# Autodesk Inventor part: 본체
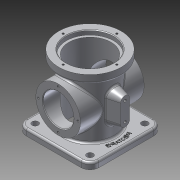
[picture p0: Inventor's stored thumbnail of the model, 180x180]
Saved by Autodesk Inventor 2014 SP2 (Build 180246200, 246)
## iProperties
Created: 2021-03
Part Number: 본체
Material: 알루미늄 6061
Document SubType Name: Modeling
Designer: 거성
Density: 2.71 g/cm^3
Appearance: 알루미늄 - 평지
Author: 거성
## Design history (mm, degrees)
sketch "스케치1"
  geometry: L1 (57, 57)-(-57, 57); L2 (-57, 57)-(-57, -57); L3 (-57, -57)-(57, -57); L4 (57, -57)-(57, 57); L5 (57, 57)-(-57, -57); L6 (-57, 57)-(57, -57); 1 further point
  constraints: 12 end point, 2 midpoint, 2 parallel, 1 horizontal, 1 perpendicular
  dimensions: "d0" = 114 distance of L3.end L2.end; "d1" = 114 distance of L2.end L1.end
extrude "돌출1" new body sketch "스케치1" stored distance "d2" = 10; taper "d3" = 0 deg
sketch "스케치2"
  geometry: C1 r 38 at (0, 0); 1 further point
  constraints: 1 centre point, 1 coincident
  dimensions: "d4" = 76 diameter of C1
extrude "돌출2" join sketch "스케치2" distance "d5" = 101; taper "d6" = 0 deg
sketch "스케치3"
  geometry: C1 r 38 at (0, 0) reference; C2 r 49 at (0, 0)
  constraints: 1 centre point, 1 coincident
  dimensions: "d7" = 98 diameter of C2
extrude "돌출3" join sketch "스케치3" distance "d8" = 13; taper "d9" = 0 deg
sketch "스케치4"
  geometry: C1 r 49 at (0, 0) reference; 1 further point
  constraints: 1 coincident
hole "구멍1" sketch "스케치4" at (0, 0) diameter "d10" = 66; stored, may be unused: countersink angle "d14" = 90 deg, drill point angle "d16" = 118 deg; dims "d11" = 6, "d12" = 74, "d13" = 7, "d15" = 8
node "작업 평면1"
sketch "스케치5"
  geometry: L1 (57, -5)-(-57, -5) reference; C1 r 35 at (0, 49); 2 further points
  constraints: 1 centre point, 1 midpoint, 1 vertical alignment
  dimensions: "d18" = 70 diameter of C1; "d19" = 54 distance from line of L1 C1.centre
extrude "돌출4" join sketch "스케치5" stored distance "d20" = 13; taper "d21" = 0 deg
sketch "스케치6"
  geometry: C1 r 35 at (0, 0) reference; 2 further points
  constraints: 1 coincident
hole "구멍2" sketch "스케치6" at (0, 0) diameter "d22" = 48; stored, may be unused: countersink angle "d26" = 90 deg, drill point angle "d28" = 118 deg; dims "d23" = 6, "d24" = 74, "d25" = 7, "d27" = 8
fillet "모깎기1" dims "d29" = 14, "d30" = 3
fillet "모깎기2" dims "d31" = 3
sketch "스케치7" dims "d32" = 62
  geometry: C1 r 35 at (0, 0) reference; 3 further points
  constraints: 2 vertical alignment, 1 coincident, 2 other
hole "구멍3" sketch "스케치7" at (0, 31) diameter "d33" = 3.242; stored, may be unused: countersink angle "d37" = 90 deg, drill point angle "d39" = 118 deg; dims "d34" = 6, "d35" = 74, "d36" = 7, "d38" = 8
sketch "스케치8" dims "d43" = 84
  geometry: C1 r 49 at (0, 0) reference; 2 further points
  constraints: 2 vertical alignment, 1 coincident, 2 other
hole "구멍4" sketch "스케치8" at (0, 42) diameter "d44" = 3.242; stored, may be unused: countersink angle "d48" = 90 deg, drill point angle "d50" = 118 deg; dims "d45" = 6, "d46" = 74, "d47" = 7, "d49" = 8
chamfer "모따기1" distance "d54" = 1; stored, may be unused: second distance "d55" = 2, angle "d56" = 45 deg
node "작업 평면2"
sketch "스케치9"
  geometry: L1 (63.5, 0)-(34.5, 0); L2 (63.5, 7)-(34.5, 7); L3 (34.5, -7)-(63.5, -7); L4 (-5, -43)-(-5, 43) reference; A1 r 7 centre (63.5, 0) between (63.5, -7) and (63.5, 7); A2 r 7 centre (34.5, 0) between (34.5, 7) and (34.5, -7); 2 further points
  constraints: 8 end point, 4 point on circle, 4 tangent, 2 centre point, 1 horizontal, 1 midpoint, 1 parallel
  dimensions: "d59" = 54 distance from line of L4 point (49, 0); "d60" = 14 distance between parallel lines of L3 L2; "d61" = 43 dimension on A2 A1
extrude "돌출5" join sketch "스케치9" distance "d62" = 20; taper "d63" = 15 deg
sketch "스케치10"
  geometry: A1 r 11 centre (43, -43) between (43, -54) and (54, -43) reference; A2 r 11 centre (43, 43) between (54, 43) and (43, 54) reference; A3 r 11 centre (-43, 43) between (-43, 54) and (-54, 43) reference; A4 r 11 centre (-43, -43) between (-54, -43) and (-43, -54) reference; 4 further points
  constraints: 4 coincident
hole "구멍5" sketch "스케치10" at (-43, 43), (43, 43), (43, -43), (-43, -43) diameter "d64" = 10; stored, may be unused: countersink angle "d68" = 90 deg, drill point angle "d70" = 118 deg; dims "d65" = 6, "d66" = 74, "d67" = 7, "d69" = 8
fillet "모깎기3" dims "d71" = 3
sketch "스케치11"
  geometry: A1 r 7 centre (0, 34.5) between (-7, 34.5) and (7, 34.5) reference; A2 r 7 centre (0, 63.5) between (7, 63.5) and (-7, 63.5) reference; 3 further points
  constraints: 2 coincident
hole "구멍6" sketch "스케치11" at (0, 63.5), (0, 34.5) diameter "d72" = 4.134; stored, may be unused: countersink angle "d76" = 90 deg, drill point angle "d78" = 118 deg; dims "d73" = 8, "d74" = 74, "d75" = 7, "d77" = 10
sketch "스케치12"
  geometry: C1 r 41 at (0, 0) reference; C2 r 50 at (0, 0)
  constraints: 1 centre point, 1 coincident, 1 other
  dimensions: "d79" = 100 diameter of C2
feature "엠보싱1" sketch "스케치12" dims "d0" = 114, "d1" = 114, "d80" = 0.5, "d81" = 0
node "솔리드1"
mirror "대칭1"
pattern_circular "원형 패턴1" dims angle "d41" = 360 deg
mirror "대칭2"
pattern_circular "원형 패턴2" dims angle "d52" = 360 deg
other parameters: "d57" = 55
